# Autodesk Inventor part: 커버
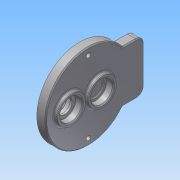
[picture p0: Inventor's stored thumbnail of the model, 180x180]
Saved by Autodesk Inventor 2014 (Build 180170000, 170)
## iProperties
Created: 2016-02
Part Number: 커버
Material: 알루미늄 6061
Document SubType Name: Modeling
Designer: mduedu
Density: 2.71 g/cm^3
Appearance: 알루미늄 - 평지
Mass: 157.248 g
Surface Area: 178.476 cm^2
Volume: 58.0249 cm^3
Author: mduedu
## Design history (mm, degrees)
sketch "스케치1"
  geometry: C1 r 43 at (0, 0); 1 further point
  constraints: 1 centre point, 1 coincident
  dimensions: "d0" = 86 diameter of C1
extrude "돌출1" new body sketch "스케치1" distance "d1" = 9; taper "d2" = 0 deg
sketch "스케치2"
  geometry: C1 r 14 at (0, 11); 1 further point
  constraints: 1 centre point, 1 vertical alignment
  dimensions: "d3" = 28 diameter of C1; "d6" = 11 distance of C1.centre point (0, 0)
extrude "돌출2" join sketch "스케치2" distance "d7" = 3; taper "d8" = 0 deg
sketch "스케치3"
  geometry: C1 r 14 at (0, -20); 1 further point
  constraints: 1 centre point, 1 vertical alignment
  dimensions: "d9" = 28 diameter of C1; "d10" = 20 distance of C1.centre point (0, 0)
extrude "돌출3" join sketch "스케치3" distance "d11" = 3; taper "d12" = 0 deg
hole "구멍1" diameter "d15" = 22; stored, may be unused: countersink angle "d19" = 90 deg, drill point angle "d21" = 0 deg; dims "d13" = 10, "d14" = 10, "d16" = 6, "d17" = 4, "d18" = 2, "d20" = 7
hole "구멍2" diameter "d24" = 18; stored, may be unused: countersink angle "d28" = 90 deg, drill point angle "d30" = 0 deg; dims "d22" = 10, "d23" = 10, "d25" = 6, "d26" = 4, "d27" = 2, "d29" = 1
hole "구멍3" diameter "d33" = 22; stored, may be unused: countersink angle "d37" = 90 deg, drill point angle "d39" = 0 deg; dims "d34" = 6, "d35" = 4, "d36" = 2, "d38" = 7, "d73" = 10, "d74" = 10
sketch "스케치7"
  geometry: L1 (-26, 34.249)-(26, 34.249); L2 (26, 34.249)-(26, 56); L3 (26, 56)-(-26, 56); L4 (-26, 56)-(-26, 34.249); A1 r 43 centre (0, 0) between (-26, 34.249) and (26, 34.249) reference; 1 further point
  constraints: 8 end point, 2 parallel, 2 point on circle, 1 horizontal, 1 perpendicular
  dimensions: "d95" = 52 distance of L2.end L3.end; "d97" = 56 distance from line of L3 point (0, 0)
extrude "돌출5" join sketch "스케치7" stored distance "d98" = 10; taper "d99" = 0 deg
sketch "스케치4"
  geometry: C1 r 14 at (0, -20) reference; C2 r 18 at (0, -20); 1 further point
  constraints: 1 centre point, 1 coincident
  dimensions: "d40" = 36 diameter of C2
extrude "돌출4" join sketch "스케치4" distance "d41" = 4; taper "d42" = 0 deg
hole "구멍4" diameter "d45" = 22; stored, may be unused: countersink angle "d49" = 90 deg, drill point angle "d51" = 0 deg; dims "d43" = 10, "d44" = 10, "d46" = 6, "d47" = 4, "d48" = 2, "d50" = 7
hole "구멍5" diameter "d54" = 15; stored, may be unused: countersink angle "d58" = 90 deg, drill point angle "d60" = 0 deg; dims "d52" = 10, "d53" = 10, "d55" = 6, "d56" = 4, "d57" = 2, "d59" = 7
fillet "모깎기1" dims "d61" = 0.3
fillet "모깎기2" dims "d62" = 2
chamfer "모따기1" distance "d63" = 1; stored, may be unused: second distance "d64" = 2, angle "d65" = 45 deg
fillet "모깎기6" dims "d88" = 2
sketch "스케치5" dims "d67" = 72
  geometry: 4 further points
  constraints: 2 horizontal alignment, 1 coincident, 5 other
  dimensions: "d71" = 360 deg dimension on point (0, 0) point (-36, 0) (derived)
fillet "모깎기4" dims "d75" = 2
sketch "스케치6"
  geometry: 2 further points
hole "구멍6" sketch "스케치6" at (36, 0), (-36, 0) diameter "d76" = 4.5; stored, may be unused: countersink angle "d80" = 90 deg, drill point angle "d82" = 0 deg; dims "d77" = 6, "d78" = 8, "d79" = 4.6, "d81" = 8
fillet "모깎기7" dims "d100" = 8, "d101" = 2
chamfer "모따기2" distance "d90" = 1; stored, may be unused: second distance "d91" = 2, angle "d92" = 45 deg
node "솔리드1"
node "절단 모서리 투영1"
